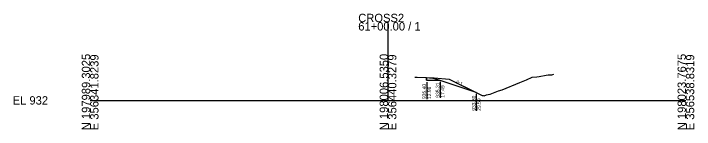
# Model space of a CAD drawing. Extents: x -26 to 203, y -10 to 14021.
# Drawn here: x -25.7 to 202.8, y 1990.3 to 2029 of the extents above; entities that cross this region are included whole.
import ezdxf

# ---------------------------------------------------------------- set-up
doc = ezdxf.new("R2010")
doc.units = 0
for name, color, linetype in [('Default', 7, 'Continuous'), ('P_E_XS_Ground', 7, 'Continuous'), ('P_XS', 7, 'Continuous'), ('P_XS_EAR_CommonGrnd', 7, 'Continuous'), ('P_XS_Lane', 7, 'Continuous'), ('P_XS_Rock', 7, 'Continuous')]:
    doc.layers.add(name, color=color, linetype=linetype)

msp = doc.modelspace()

# ---------------------------------------------------------------- linework, layer by layer
at = {"layer": 'Default'}
for p, q in [((100, 2000), (100, 2026.2)), ((0, 2000), (100, 2000)), ((100, 2000), (200, 2000))]:
    msp.add_line(p, q, dxfattribs=at)
at = {"layer": 'P_E_XS_Ground'}
for p, q in [((108.96, 2007.79), (109.74, 2007.77)), ((109.74, 2007.77), (115.5, 2007.54)), ((115.5, 2007.54), (120.5, 2007.14)), ((120.5, 2007.14), (131.55, 2001.61)), ((144.21, 2005.94), (146.47, 2006.89)), ((146.47, 2006.89), (148.34, 2007.78)), ((148.34, 2007.78), (149.92, 2007.92)), ((149.92, 2007.92), (150.77, 2008.05)), ((150.77, 2008.05), (153.1, 2008.41)), ((153.1, 2008.41), (153.71, 2008.55)), ((153.71, 2008.55), (155.02, 2008.6)), ((155.02, 2008.6), (155.7, 2008.73)), ((138.27, 2003.52), (144.21, 2005.94)), ((133.62, 2001.94), (134.26, 2002.11)), ((134.26, 2002.11), (137.12, 2003.21)), ((137.12, 2003.21), (138.27, 2003.52)), ((131.55, 2001.61), (131.9, 2001.62)), ((131.9, 2001.62), (132.25, 2001.57)), ((132.25, 2001.57), (133.08, 2001.86)), ((133.08, 2001.86), (133.62, 2001.94))]:
    msp.add_line(p, q, dxfattribs=at)
at = {"layer": 'P_XS'}
for p, q in [((108.96, 2007.79), (112.96, 2007.63)), ((112.96, 2007.63), (114.96, 2007.47)), ((117.49, 2006.62), (114.96, 2007.47))]:
    msp.add_line(p, q, dxfattribs=at)
at = {"layer": 'P_XS_EAR_CommonGrnd'}
msp.add_lwpolyline([(115.5, 2007.54), (120.5, 2007.14), (129.59, 2002.59), (117.49, 2006.62), (112.96, 2006.81), (112.96, 2007.64)], close=True, dxfattribs=at)
at = {"layer": 'P_XS_Lane'}
for p, q in [((112.96, 2007.64), (112.96, 2006.81)), ((112.96, 2006.81), (117.49, 2006.62)), ((129.59, 2002.59), (117.49, 2006.62))]:
    msp.add_line(p, q, dxfattribs=at)
at = {"layer": 'P_XS_Rock'}
for p, q in [((112.99, 2006.15), (112.99, 2000.45)), ((117.48, 2006.19), (117.48, 2000.9)), ((129.63, 2002.22), (129.63, 1996.53))]:
    msp.add_line(p, q, dxfattribs=at)

# ---------------------------------------------------------------- texts
at = {"layer": 'Default'}
for s, p in [('CROSS2', (90, 2026.2)), ('61+00.00 / 1', (90, 2023.4)), ('EL 932', (-26, 1998.6))]:
    msp.add_text(s, height=2.8, dxfattribs=at).set_placement(p)
for s, p in [('N 197989.3025', (0, 1990)), ('E 356341.8239', (2.8, 1990)), ('N 198006.5350', (100, 1990)), ('E 356440.3279', (102.8, 1990)), ('N 198023.7675', (200, 1990)), ('E 356538.8319', (202.8, 1990))]:
    msp.add_text(s, height=2.8, rotation=90, dxfattribs=at).set_placement(p)
at = {"layer": 'P_XS_Rock'}
for s, rotation, p in [('6:1', 341.5651, (122.71, 2005.63)), ('935.40', 90, (112.74, 2000.45)), ('12.96', 90, (114.44, 2000.45)), ('935.31', 90, (117.23, 2000.9)), ('17.49', 90, (118.93, 2000.9)), ('933.30', 90, (129.38, 1996.53)), ('29.59', 90, (131.08, 1996.53))]:
    msp.add_text(s, height=1.2, rotation=rotation, dxfattribs=at).set_placement(p)

doc.saveas('drawing.dxf')
